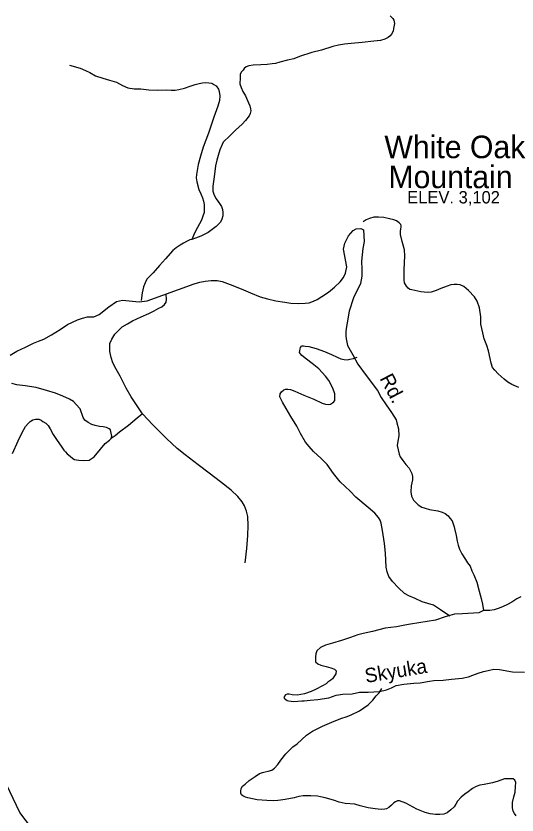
# Model space of a CAD drawing. Extents: x 990631 to 1056237, y 535999 to 585651.
# Drawn here: x 1036869 to 1040197, y 568418 to 573727 of the extents above; entities that cross this region are included whole.
import ezdxf

# ---------------------------------------------------------------- set-up
doc = ezdxf.new("R2010")
doc.units = 0
for name, color, linetype in [('Exist Geographical Mountain Summit Label', 7, 'Continuous'), ('Exist Hydrographic Creek Single Shore', 7, 'Continuous'), ('Exist Road Non-System Type 51', 7, 'Continuous'), ('Exist Road Secondary Type 20 Attributed', 7, 'Continuous'), ('Exist Road Secondary Type 51 Attributed', 7, 'Continuous'), ('Exist Road Secondary Type 51 Label', 7, 'Continuous'), ('Exist Survey Geodetic Marker Label', 7, 'Continuous')]:
    doc.layers.add(name, color=color, linetype=linetype)

msp = doc.modelspace()

# ---------------------------------------------------------------- linework, layer by layer
at = {"layer": 'Exist Hydrographic Creek Single Shore'}
msp.add_lwpolyline([(1037246.9, 567972), (1036894.9, 568435.2), (1036738.3, 568756.8), (1036725, 568858.8), (1036558.9, 569137.8), (1036345.1, 569237.3), (1036281.1, 569320.7), (1036260, 569439.2), (1036313.4, 569535)], dxfattribs=at)
at = {"layer": 'Exist Road Non-System Type 51'}
for points in [[(1039355.2, 573727), (1039372.6, 573710.5), (1039378.2, 573698.3), (1039383.6, 573676), (1039376.5, 573644.4), (1039374, 573626.4), (1039363.2, 573606.6), (1039354.9, 573595), (1039340.5, 573583.5), (1039318, 573572.1), (1039289.9, 573563.1), (1039245.6, 573560.6), (1039167.4, 573550.9), (1039095, 573543.2), (1039050.9, 573538.7), (1039010.5, 573532.1), (1038972.3, 573523.2), (1038897.4, 573499.5), (1038834.9, 573483.6), (1038752.2, 573458.2), (1038713.7, 573443.4), (1038673.2, 573432.8), (1038620.8, 573420.5), (1038592.4, 573411.2), (1038570.3, 573408.1), (1038538.2, 573405.1), (1038494.2, 573402.4), (1038444.1, 573400), (1038415.8, 573395), (1038397.7, 573389.5), (1038385.2, 573378), (1038377, 573368.1), (1038364.5, 573352.6), (1038358, 573338.7), (1038357.2, 573316.7), (1038356, 573276.7), (1038363.3, 573252.6), (1038376.4, 573226.1), (1038393.4, 573195.5), (1038412.1, 573151), (1038421.5, 573130.6), (1038426.7, 573110.4), (1038428.2, 573096.4), (1038423.6, 573078.5), (1038417.1, 573062.6), (1038392.3, 573031.5), (1038371.4, 573008.1), (1038326.2, 572967.6), (1038280.6, 572922.9), (1038255.8, 572899.8), (1038245.5, 572888), (1038239, 572872.3), (1038221.9, 572836.9), (1038212.5, 572799), (1038201.7, 572769.4), (1038194.4, 572731.6), (1038186.1, 572657.7), (1038176, 572596.1), (1038177, 572562.1), (1038184.2, 572535.7), (1038197.4, 572513.2), (1038220.3, 572480.6), (1038233.7, 572460.1), (1038241.2, 572441.9), (1038242.6, 572421.9), (1038241.9, 572399.9), (1038235, 572376), (1038226.4, 572356.2), (1038197.4, 572327.2), (1038170.8, 572308.1), (1038144.2, 572288.8), (1038097.3, 572264.3), (1038060.9, 572251.5), (1038036.7, 572242.4)], [(1037223.3, 573401.1), (1037294.7, 573380.9), (1037330.2, 573363.8), (1037359.7, 573350.8), (1037397.1, 573329.6), (1037444.6, 573314.1), (1037490.2, 573300.5), (1037535.7, 573287), (1037577.1, 573265.8), (1037610.6, 573250.7), (1037652.5, 573243.3), (1037698.5, 573241.9), (1037750.4, 573236.1), (1037808.3, 573234.3), (1037866.4, 573236.6), (1037900.4, 573233.3), (1037926.4, 573234.5), (1037950.5, 573237.7), (1037988.9, 573248.5), (1038025.4, 573261.4), (1038059.6, 573272.3), (1038085.9, 573277.4), (1038108, 573282.7), (1038130.1, 573286.1), (1038150, 573283.5), (1038170, 573280.7), (1038183.8, 573272.2), (1038199.4, 573261.9), (1038212.8, 573241.4), (1038218.3, 573225.1), (1038223.3, 573197), (1038220.3, 573165), (1038209.1, 573127.4), (1038182.6, 573054.1), (1038147.3, 572949.2), (1038112.2, 572854.3), (1038094.4, 572794.8), (1038078.7, 572739.3), (1038071.3, 572701.4), (1038068.6, 572673.7), (1038065.7, 572651.7), (1038069, 572625.4), (1038083.4, 572574.9), (1038096.4, 572544.7), (1038107.4, 572518.2), (1038114.8, 572495.9), (1038118.2, 572473.8), (1038119.2, 572443.8), (1038118.5, 572421.8), (1038109.6, 572396.1), (1038100.9, 572370.3), (1038075.3, 572321.2), (1038053.9, 572283.8), (1038036.7, 572242.4)], [(1040208.4, 571257.9), (1040163, 571277.5), (1040135.5, 571294.4), (1040112.3, 571313.1), (1040071.4, 571348.5), (1040050.1, 571373.2), (1040034.6, 571391.7), (1040025.6, 571419.9), (1040018.7, 571452.2), (1040008.3, 571502.7), (1039997.3, 571536.9), (1039978.6, 571581.7), (1039970, 571621.9), (1039955.8, 571680.4), (1039955.4, 571728.4), (1039947.2, 571786.8), (1039932.6, 571831.3), (1039913.6, 571859.9), (1039874.9, 571903.1), (1039843.8, 571930.1), (1039820.2, 571941), (1039800.3, 571943.6), (1039780.2, 571942.2), (1039758.2, 571940.8), (1039731.8, 571931.8), (1039691.3, 571917), (1039660.8, 571902), (1039626.3, 571891.1), (1039602.3, 571890), (1039558.4, 571895.2), (1039498.8, 571907.2), (1039484.9, 571909.7), (1039473.2, 571918), (1039461.7, 571932.4), (1039450.4, 571954.8), (1039446.9, 571970.9), (1039447.1, 572040.9), (1039451.9, 572132.9), (1039449.4, 572172.9), (1039433, 572227.5), (1039422.6, 572275.9), (1039423.2, 572295.9), (1039425.8, 572315.9), (1039428.2, 572323.8), (1039428.3, 572331.8), (1039424.7, 572341.9), (1039414.9, 572352.1), (1039395.4, 572364.9), (1039377.8, 572373.5), (1039349.9, 572380.2), (1039312, 572387.6), (1039276.3, 572390.7), (1039246.2, 572389.7), (1039217.9, 572382.5), (1039195.5, 572373.3), (1039175.2, 572359.9)], [(1038036.7, 572242.4), (1038022.4, 572238.8), (1038002.2, 572229.4), (1037981.8, 572218), (1037959.3, 572204.7), (1037932.7, 572187.6), (1037910.1, 572168.3), (1037862.4, 572113.8), (1037822.9, 572069), (1037779.3, 572020.4), (1037756.7, 571999.1), (1037737.9, 571977.7), (1037727.2, 571954.1), (1037716.3, 571928.3), (1037707.1, 571888.6), (1037699.4, 571836.8)], [(1037709.3, 571083.9), (1037705.4, 571090.2), (1037672.9, 571137.2), (1037632.9, 571196.5), (1037600.7, 571253.5), (1037561.2, 571333), (1037534.6, 571379.7), (1037512, 571422.6), (1037501.1, 571456.8), (1037492.3, 571497.2), (1037491.3, 571527.2), (1037492.2, 571551.2), (1037505, 571578.8), (1037526, 571612.2), (1037549, 571637.5), (1037573.7, 571662.6), (1037608.5, 571681.5), (1037643.1, 571702.5), (1037700, 571728.7), (1037750.7, 571751.1), (1037787.3, 571768), (1037817.8, 571785), (1037838.2, 571794.4), (1037854.7, 571809.8), (1037867.2, 571825.4), (1037867.8, 571845.4), (1037866.9, 571877.4)], [(1039751.5, 569739.5), (1039688.8, 569781.6), (1039641.7, 569811.2), (1039566.4, 569835.5), (1039521, 569857), (1039477.6, 569874.5), (1039450, 569889.3), (1039409.4, 569926.7), (1039370.6, 569969.9), (1039345.7, 570002.8), (1039334.7, 570033.2), (1039327.7, 570065.4), (1039322.6, 570157.7), (1039316.7, 570221.9), (1039303.4, 570308.4), (1039295, 570356.8), (1039287.6, 570376.9), (1039276.2, 570395.3), (1039253.1, 570424), (1039208.3, 570461.5), (1039126.4, 570530.2), (1039087.6, 570569.4), (1039021.6, 570631.5), (1038977.3, 570687.1), (1038935.3, 570746.5), (1038896.5, 570785.7), (1038846, 570833.4), (1038815.1, 570866.4), (1038791.8, 570895.1), (1038757.8, 570952.4), (1038733.4, 571001.1), (1038695.3, 571066.5), (1038663.1, 571119.5), (1038638.3, 571160.3), (1038627, 571182.7), (1038621.5, 571196.8), (1038624.1, 571216.8), (1038632.5, 571230.6), (1038647, 571244.1), (1038659.1, 571247.7), (1038675.1, 571247.1), (1038693, 571244.6), (1038720.8, 571233.6), (1038779.9, 571207.8), (1038847.2, 571181.7), (1038902.3, 571153.7), (1038924.2, 571147.1), (1038944.1, 571144.5), (1038958.2, 571148), (1038970.3, 571155.6), (1038980.7, 571163.4), (1038986.9, 571173.1), (1038987.5, 571191), (1038986.4, 571217.1), (1038973.5, 571253.6), (1038947.1, 571304.5), (1038924.1, 571333.2), (1038879.7, 571382.7), (1038836.8, 571418.2), (1038797.5, 571447.4), (1038768.4, 571470.4), (1038758.8, 571482.6), (1038753, 571490.9), (1038753.4, 571502.9), (1038755.7, 571514.8), (1038758.1, 571524.6), (1038764.4, 571532.5), (1038770.5, 571534.3), (1038778.5, 571536), (1038790.5, 571533.7), (1038814.4, 571530.9), (1038862, 571517.3), (1038917.4, 571497.6), (1038964.8, 571478), (1039002.3, 571460.9), (1039025.9, 571450), (1039047.8, 571445.3), (1039067.7, 571442.7), (1039085.8, 571446.2), (1039109.9, 571451.3), (1039134.3, 571460.6)], [(1037709.3, 571083.9), (1037674.3, 571055), (1037616.7, 571006.9), (1037557.1, 570960.7), (1037526.5, 570937.7), (1037499.9, 570920.6)], [(1038390, 570093.4), (1038401.1, 570189.3), (1038407.8, 570274.9), (1038412, 570340.9), (1038407.8, 570401.2), (1038400.9, 570437.3), (1038386.2, 570471.9), (1038370.9, 570498.4), (1038342, 570533.4), (1038297.5, 570576.9), (1038227.1, 570631.1), (1038152.9, 570689.4), (1038078.6, 570743.9), (1037992.7, 570810.7), (1037940.1, 570852.4), (1037868, 570918.8), (1037777, 571009.7), (1037709.3, 571083.9)], [(1040221.9, 569868.5), (1040195.4, 569853.5), (1040162.7, 569832.5), (1040134.2, 569817.3), (1040099.7, 569800.6), (1040071.2, 569789.3), (1040045, 569780.3), (1040017, 569777), (1039974.7, 569776.5)], [(1038535.5, 568513.7), (1038471.5, 568517.8), (1038439.7, 568524.8), (1038408, 568531.9), (1038392.1, 568536.4), (1038376.3, 568544.9), (1038366.6, 568553.1), (1038362.8, 568563.2), (1038361.3, 568577.2), (1038363.9, 568595.2), (1038372.3, 568609), (1038390.8, 568622.5), (1038417.5, 568647.5), (1038458.5, 568674.3), (1038485.1, 568693.4), (1038505.4, 568700.8), (1038523.5, 568704.2), (1038543.6, 568709.6), (1038568, 568716.7), (1038586.4, 568728.2), (1038607.1, 568753.6), (1038628.1, 568783), (1038661.4, 568823.9), (1038706.9, 568870.4), (1038735.7, 568891.6), (1038797.5, 568947.6), (1038838.4, 568974.4), (1038905.5, 569008.3), (1038966.5, 569034.3), (1039027.2, 569060.2), (1039067.7, 569073), (1039096.1, 569084.1), (1039150.9, 569110.4), (1039179.5, 569129.4), (1039208.3, 569150.6), (1039239.3, 569181.6), (1039262.1, 569209), (1039280.9, 569230.4), (1039299.7, 569257.8)], [(1040191.2, 568412.6), (1040179.7, 568427), (1040172.2, 568443.2), (1040166.8, 568465.3), (1040166.2, 568501.3), (1040175.3, 568539.2), (1040184.3, 568569), (1040187.5, 568606.8), (1040188.3, 568634.7), (1040182.7, 568649.1), (1040171.1, 568657.3), (1040157.1, 568657.8), (1040139.1, 568658.3), (1040113.1, 568657.3), (1040070.6, 568642.7), (1040034.2, 568631.8), (1039977.7, 568621.6), (1039949.6, 568616.5), (1039925.2, 568607.2), (1039900.9, 568593.9), (1039872.1, 568572.9), (1039849.6, 568555.5), (1039825, 568536.4), (1039802.2, 568511.1), (1039789.4, 568489.5), (1039778.9, 568471.9), (1039758.3, 568452.5), (1039733.7, 568433.2), (1039711.3, 568424.1), (1039685.2, 568420.8), (1039655.2, 568421.8), (1039619.3, 568424.9), (1039587.6, 568433.9), (1039532.3, 568457.7), (1039457.4, 568496.2), (1039415.9, 568511.4), (1039401.9, 568511.9), (1039389.6, 568506.3), (1039377.5, 568498.8), (1039362.9, 568483.3), (1039344.4, 568467.8), (1039330.3, 568460.1), (1039318, 568456.6), (1039294, 568455.5), (1039254, 568458.7), (1039208.3, 568466.2), (1039154.8, 568477.9), (1039119, 568489), (1039055.1, 568495.1), (1039015.4, 568504.3), (1038977.7, 568515.6), (1038922.2, 568531.4), (1038892.5, 568538.3), (1038870.6, 568543), (1038826.6, 568544.5), (1038776.6, 568546.1), (1038748.5, 568540.8), (1038716.1, 568531.9), (1038657.7, 568521.9), (1038625.6, 568516.9), (1038607.5, 568513.5), (1038579.5, 568512.2), (1038535.5, 568513.7)]]:
    msp.add_lwpolyline(points, dxfattribs=at)
at = {"layer": 'Exist Road Secondary Type 20 Attributed'}
for points in [[(1036873.9, 571499), (1036930.9, 571527.3), (1036983.9, 571553.6), (1037018.4, 571566.6), (1037052.8, 571579.5), (1037103.6, 571607.7), (1037163, 571643.9), (1037210, 571676.4), (1037244.6, 571693.3), (1037277.1, 571708.2), (1037309.3, 571719.2), (1037343.7, 571728.1), (1037386.3, 571727.5), (1037422, 571744.5), (1037485.9, 571794.8), (1037536.9, 571830.5), (1037575.2, 571839.9), (1037620.3, 571833.9), (1037686.6, 571828.8), (1037739.4, 571834.8), (1038053.2, 571947.5), (1038089.6, 571958.4), (1038125.7, 571965.3), (1038166, 571969.9), (1038204, 571968.7), (1038237.7, 571963.6), (1038291.2, 571943.9), (1038364.4, 571913.6), (1038427.5, 571887.6), (1038490.8, 571861.5), (1038538.3, 571847.9), (1038593.9, 571834.2), (1038653.7, 571826.2), (1038695.4, 571819), (1038743.4, 571817.4), (1038789.6, 571817.9), (1038815.7, 571821.1), (1038845.9, 571832.1), (1038870.3, 571843.2), (1038900.9, 571862.2), (1038943.9, 571891), (1038985, 571925.8), (1039022.1, 571960.4), (1039045.1, 571989.8), (1039058.1, 572019.3), (1039065.3, 572059.2), (1039045.3, 572177), (1039052.1, 572217.8), (1039077.6, 572266.4), (1039108.2, 572302.1), (1039127.8, 572312.3), (1039159.3, 572314.9), (1039178, 572307.2), (1039181, 572229.6), (1039173.7, 572181.2), (1039163.5, 572097), (1039165.2, 572045), (1039166.1, 571997.4), (1039156.7, 571950.5), (1039111.6, 571855.2), (1039081.8, 571765.8), (1039068.2, 571689.2), (1039064, 571663.7), (1039058.9, 571631.3), (1039060.6, 571601.5), (1039061.4, 571581.1), (1039071.6, 571538.5), (1039106.5, 571474.7), (1039140.5, 571414.3), (1039195.8, 571339.3), (1039269.3, 571238), (1039293.8, 571191.3), (1039328.2, 571144.2), (1039362.6, 571093.1), (1039393, 571044), (1039399.2, 571022.7), (1039410.2, 570983.5), (1039411.1, 570936.7), (1039405.1, 570901), (1039401.7, 570872.9), (1039413.8, 570815.1), (1039421.1, 570797), (1039438.4, 570772.4), (1039457.7, 570747.6), (1039480.8, 570723), (1039490.2, 570704.6), (1039497.7, 570686.4), (1039503.1, 570666.3), (1039502.1, 570644.7), (1039494.4, 570604.7), (1039491, 570564.7), (1039497, 570536.6)], [(1036829.2, 571472.5), (1036873.9, 571499)], [(1036846.3, 570819.5), (1036883, 570904.4), (1036910.7, 570959.5), (1036932.1, 570998.9), (1036948.7, 571018.4), (1036963.2, 571031.9), (1036981.4, 571043.3), (1036997.7, 571048.8), (1037019.7, 571048.1), (1037035.4, 571041.6), (1037047.2, 571033.2), (1037066.8, 571020.6), (1037082.3, 571006.1), (1037095.7, 570983.6), (1037116.5, 570947), (1037141.1, 570906), (1037168, 570869.1), (1037187.2, 570842.5), (1037197.7, 570830.4), (1037208.4, 570817.9), (1037227.8, 570801.3), (1037245.3, 570786.7), (1037257.2, 570780.3), (1037271.2, 570777.8), (1037286.8, 570775.8), (1037316.6, 570774.1), (1037354, 570776.7), (1037388.9, 570798.8), (1037430.6, 570849.9), (1037460.8, 570885.8), (1037489.5, 570908.8), (1037499.9, 570920.6), (1037504.4, 570934.6), (1037501, 570954.6), (1037495.7, 570976.7), (1037488, 570984.9), (1037470.2, 570993.7), (1037448.2, 570996.3), (1037424.3, 570999), (1037394.6, 571006), (1037372.7, 571012.6), (1037348, 571026.1), (1037326.8, 571042.3), (1037314, 571060.1), (1037294, 571117.3), (1037269, 571146.2), (1037251.5, 571164.7), (1037224.1, 571181.7), (1037180.7, 571201), (1037131.2, 571220.6), (1037071.8, 571238.6), (1037002.4, 571258.8), (1036928.7, 571269), (1036874.9, 571276.9), (1036841.3, 571286)]]:
    msp.add_lwpolyline(points, dxfattribs=at)
at = {"layer": 'Exist Road Secondary Type 51 Attributed'}
for points in [[(1039497, 570536.6), (1039509.8, 570509.4), (1039526.8, 570492.3), (1039541.2, 570479.6), (1039564.6, 570464), (1039586.6, 570456.4), (1039615.2, 570448.4), (1039671.3, 570438.1), (1039698.8, 570430), (1039719.4, 570420.9), (1039738.9, 570404.8), (1039750.3, 570391.1), (1039765.2, 570372.8), (1039773.3, 570353.3), (1039779, 570333.8), (1039782.4, 570321.2), (1039792.7, 570274.7), (1039799.6, 570238.4), (1039806.6, 570210.2), (1039813.9, 570183.9), (1039830.9, 570153.3), (1039853.7, 570116.6), (1039868.9, 570094.1), (1039886.3, 570071.6), (1039897.2, 570041.1), (1039910.5, 570014.7), (1039928.9, 569966.1), (1039944.9, 569905.5), (1039959.4, 569857), (1039968.2, 569818.6), (1039974.7, 569776.5), (1039944.1, 569762.4), (1039834.2, 569755.5), (1039782.1, 569753.2), (1039719.7, 569735.5), (1039655, 569713.1), (1039489.6, 569686.8), (1039451.8, 569679.3), (1039396.8, 569667.3), (1039320.7, 569658.7), (1039237.7, 569636.9), (1039174.7, 569624.3), (1039140.4, 569614.6), (1039090, 569596.8), (1039029.9, 569578.5), (1038970.9, 569559.6), (1038925.7, 569547), (1038890.7, 569532.1), (1038867.3, 569508.1), (1038861, 569488.6), (1038858.2, 569470), (1038857.6, 569450), (1038859.1, 569436), (1038874.1, 569422.9), (1038894.5, 569412.8), (1038928.1, 569403.8), (1038960, 569396.7), (1038983.8, 569388), (1038995.5, 569375.7), (1038992.7, 569355.1), (1038980.1, 569335.1), (1038972, 569323.6), (1038959.4, 569313.3), (1038941.1, 569301.3), (1038928.6, 569289.7), (1038903.9, 569276.6), (1038862.7, 569254.9), (1038828.3, 569238.3), (1038784.8, 569222.2), (1038735.6, 569215.3), (1038703, 569217.6), (1038684.1, 569220.5), (1038670.2, 569221.9), (1038660, 569216.3), (1038651.7, 569208.4), (1038647.5, 569198.5), (1038651.4, 569191.9), (1038655.5, 569190.1), (1038661.8, 569186.1), (1038670.3, 569179.8), (1038679.5, 569175.8), (1038715, 569172.9), (1038768.2, 569175.8), (1038782.9, 569176.2), (1038823.2, 569181.5), (1038874.1, 569185.6), (1038946.3, 569197), (1038995.5, 569214.8)], [(1038995.5, 569214.8), (1039039, 569220.5), (1039100.9, 569223.9), (1039151.2, 569234.2), (1039207.3, 569234.2), (1039284.1, 569238.3), (1039329.9, 569249.7), (1039363.6, 569264), (1039394.5, 569278.7), (1039444.7, 569287.1), (1039511.3, 569294.4), (1039552.6, 569297.3), (1039615.5, 569307.6), (1039643.7, 569310.7), (1039705.8, 569314.7), (1039762.1, 569321), (1039832.3, 569326.8), (1039874.6, 569335.3), (1039903.1, 569346.5), (1039939.6, 569361.2), (1039973.8, 569372.1), (1040004.2, 569379.3), (1040042.3, 569386), (1040080.3, 569384.8), (1040167.1, 569369.7), (1040247.3, 569367.4)]]:
    msp.add_lwpolyline(points, dxfattribs=at)

# ---------------------------------------------------------------- texts
at = {"layer": 'Exist Geographical Mountain Summit Label'}
for s, p in [('White Oak', (1039315.6, 572782.2)), ('Mountain', (1039342.6, 572583))]:
    msp.add_text(s, height=150, dxfattribs=at).set_placement(p)
at = {"layer": 'Exist Road Secondary Type 51 Label'}
for s, rotation, p in [('Rd.', 297.648, (1039282.2, 571319.5)), ('Skyuka', 9.4963, (1039193.8, 569295.1))]:
    msp.add_text(s, height=95, rotation=rotation, dxfattribs=at).set_placement(p)
at = {"layer": 'Exist Survey Geodetic Marker Label'}
msp.add_text('ELEV. 3,102', height=82.021, dxfattribs=at).set_placement((1039467.3, 572481.6))

doc.saveas('drawing.dxf')
